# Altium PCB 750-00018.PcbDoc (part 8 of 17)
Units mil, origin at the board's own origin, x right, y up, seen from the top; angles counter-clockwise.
Board outline 7086.64 x 6299.21 mil, 8 copper layers (Top Layer, L2, L3, L4, L5, L6, L7, Bottom Layer), stack 60.6 mil thick; 1356 components, 1054 nets, 4851 pads, 4296 vias.
Unrouted connection lines stored in the file: 12.
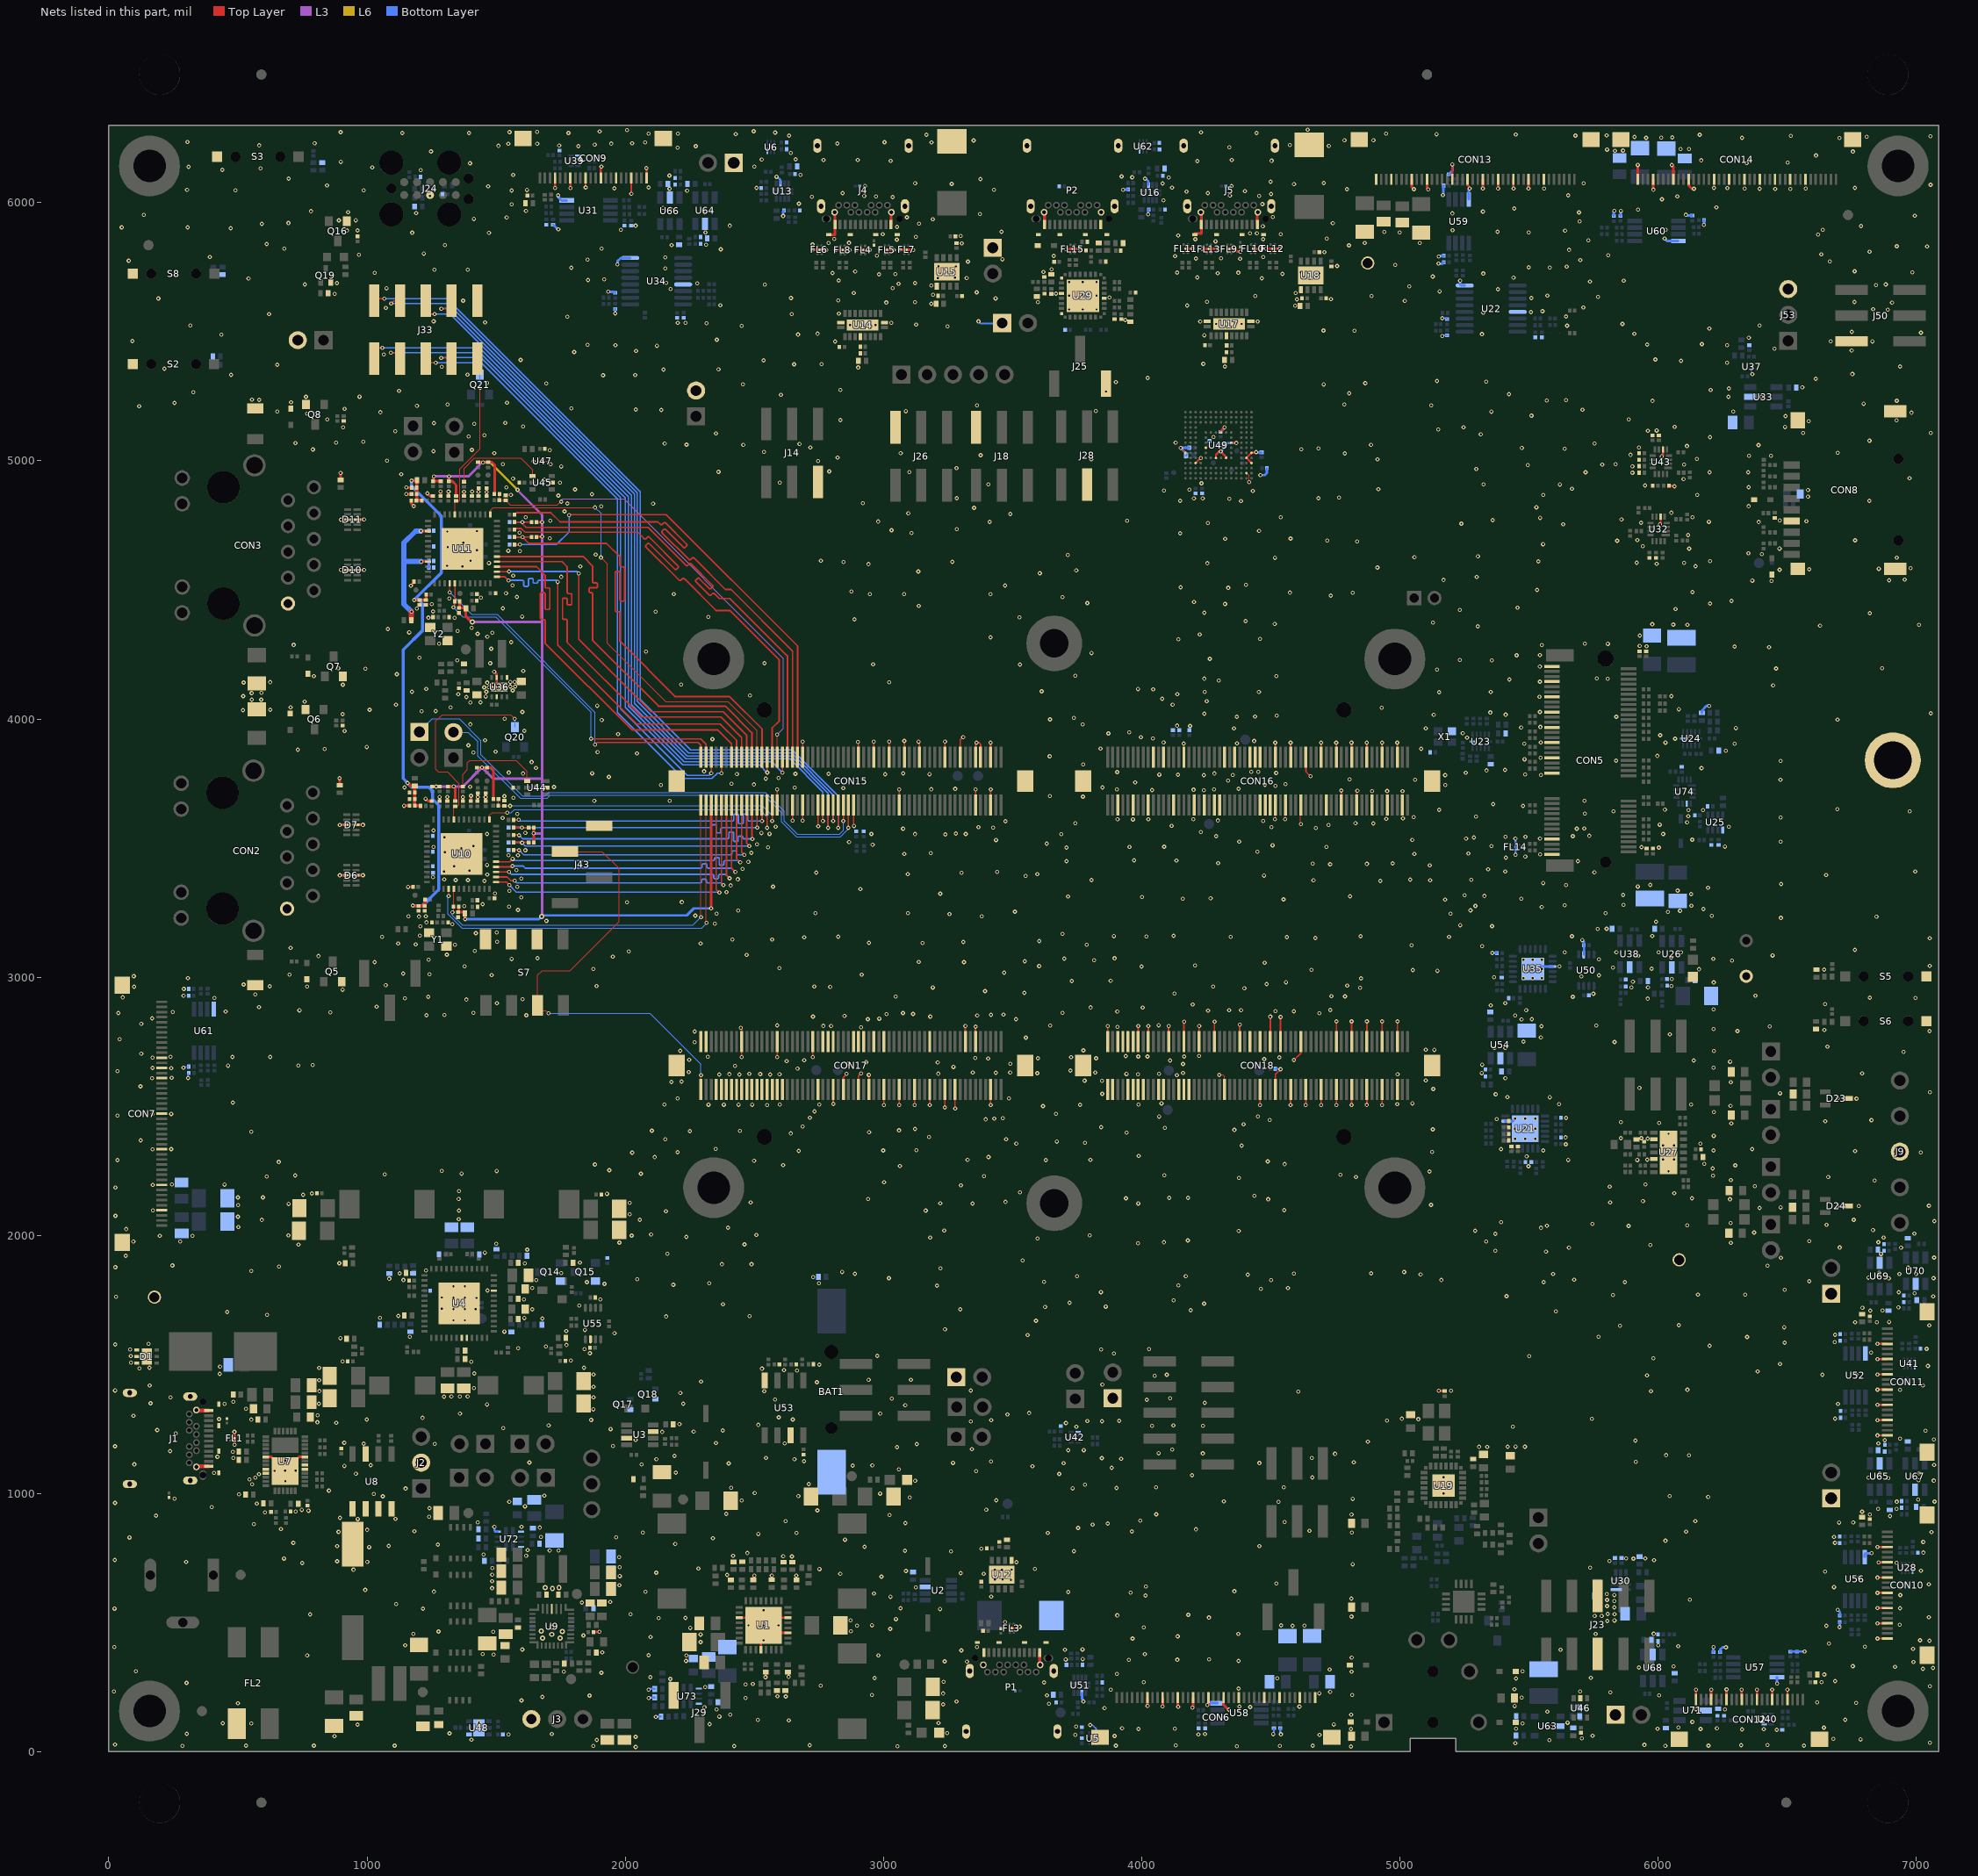
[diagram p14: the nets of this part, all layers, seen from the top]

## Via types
v1: diameter 16, hole 8, Top Layer to Bottom Layer, tented both sides, 3994 vias
v2: diameter 20, hole 10, Top Layer to Bottom Layer, tented both sides, 266 vias
v3: diameter 14, hole 7.87, Top Layer to Bottom Layer, tented both sides, 24 vias
v4: diameter 22, hole 12, Top Layer to Bottom Layer, tented both sides, 8 vias
v5: diameter 24, hole 12, Top Layer to Bottom Layer, tented both sides, 4 vias

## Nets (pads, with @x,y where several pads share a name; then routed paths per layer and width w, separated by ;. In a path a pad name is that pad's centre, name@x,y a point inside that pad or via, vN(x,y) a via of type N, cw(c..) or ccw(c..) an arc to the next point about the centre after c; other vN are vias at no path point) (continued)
ETH1_VDDA_1V8: C126.2 C127.1 C128.1 C129.1 C130.1 C152.2 C153.1 C154.1 C155.1 C156.1 FB2.2 FB4.2 R76.1 R77.1 R109.1 R110.1 | length 2343.3
  Top Layer w10: v1(1182.52,4461.06) 1182.76,4461.3 C155.1@1227.55,4461.3 1228.79,4462.53 R109.1@1228.79,4482.59
  Top Layer w12: v1(1157.01,3752.13) 1168.43,3740.72 FB2.2@1184.36,3740.72 C126.2@1184.36,3714.83 ; v1(1172.22,4923.13) 1173.37,4924.29 FB4.2@1193.87,4924.29 1192.04,4922.46 C152.2@1192.04,4896.05 1192.04,4872.01 1192.03,4847.98 C156.1@1191.83,4847.79 ; v1(1176.99,3277.43) 1198.48,3277.43 C128.1@1199.45,3276.46 ; C126.2@1184.47,3714.83 C127.1@1184.46,3689.91 C129.1@1184.46,3664.62 1206.53,3664.62 R77.1@1207.75,3663.4 ; C156.1@1191.77,4847.72 C156.1@1191.83,4847.79 ; C128.1@1199.46,3276.44 C130.1@1223.51,3276.44 1224.85,3277.78 R76.1@1224.85,3300.28 ; R110.1@1212.96,4847.79 C156.1@1191.83,4847.79
  Bottom Layer w12: v1(1172.22,4923.13) 1172.22,4901.66 1287.77,4786.11 1287.77,4566.31 v1(1182.52,4461.06) 1199,4461.06 1215.45,4444.6 1215.45,4343.33 1139.41,4267.29 1139.41,3769.73 v1(1157.01,3752.13) 1174.1,3735.04 1240.29,3735.04 1253.93,3721.4 1253.93,3690.35 1277.82,3666.46 1277.82,3339.79 1215.46,3277.43 v1(1176.99,3277.43)
ETH1_VDDA_2V5: C157.2 C158.1 C159.1 FB17.2 U11.3 U11.9 | length 603.7
  Top Layer w10: v1(1208.97,4727.97) 1209.06,4727.88 U11.3@1235.62,4727.88 ; v1(1209.42,4609.98) 1209.63,4609.77 U11.9@1235.62,4609.77
  Top Layer w20: FB17.2@1171.69,4382.32 1171.69,4414.81 v1(1172.16,4415.27)
  Bottom Layer w10: v1(1208.97,4727.97) 1210.23,4729.23 C157.2@1238.84,4729.23 ; v1(1209.42,4609.98) 1211.53,4612.08 C158.1@1238.84,4612.08 C159.1@1238.84,4586.7 C159.1@1238.84,4586.7
  Bottom Layer w20: v1(1172.16,4415.27) 1142.74,4444.68 1142.74,4610.83 ; v1(1208.97,4727.97) 1188.14,4727.97 1142.74,4682.58 1142.74,4610.83 ; v1(1209.42,4609.98) 1143.6,4609.98 1142.74,4610.83
ETH_A_(R)(G)MII_COL: CON15.50 J33.5 | length 3000.7
  Top Layer w5: J33.5@1227.36,5620.08 1227.36,5578.09 1236.71,5568.73 v1(1261.51,5568.73) ; v1@2765.75,3604.75 CON15.50@2765.75,3666.88
  Bottom Layer w5: v1(1261.51,5568.73) 1321.48,5568.73 2024.19,4866.02 2024.19,4055.28 2233.92,3845.55 2637.36,3845.55 2765.66,3717.26 2765.66,3619.21 v1(2765.66,3604.65)
ETH_A_(R)(G)MII_CRS: CON15.52 J33.3 | length 3044.6
  Top Layer w5: v1(1287.25,5588.73) 1326.4,5588.73 1327.36,5589.69 J33.3@1327.36,5620.08 ; v1(2785.34,3578.53) 2785.44,3578.62 CON15.52@2785.44,3666.88
  Bottom Layer w5: v1(1287.25,5588.73) 1288.93,5590.41 1315.62,5590.41 2035.21,4870.82 2035.21,4060.61 2239.9,3855.92 2642.01,3855.92 2785.34,3712.59 2785.34,3629.5 v1(2785.34,3578.53)
ETH_A_(R)(G)MII_RX_CLK: C123.1 CON15.18 R83.1 | length 1140.6
  Top Layer w6: R83.1@1567.63,3492.99 1587.57,3492.99 v1(1588.53,3492.03) ; CON15.18@2450.79,3666.88 2450.79,3484.42 v1(2461.15,3474.06)
  Bottom Layer w6: C123.1@1567.62,3492.99 1587.57,3492.99 v1(1588.53,3492.03) 1606.51,3474.06 2404.16,3474.06 2407.16,3474.06 ccw(c2407.16,3480.06) 2413.16,3480.06 2413.16,3484.47 cw(c2417.66,3484.47) 2417.66,3488.97 2426.66,3488.97 cw(c2426.66,3484.47) 2431.16,3484.47 2431.16,3480.06 ccw(c2437.16,3480.06) 2437.16,3474.06 2451.85,3474.06 v1(2461.15,3474.06)
ETH_A_(R)(G)MII_RX_DV(_ER): CON15.30 R80.1 R100.2 R101.1 | length 1185
  Top Layer w4: R100.2@1508.75,3689.35 1508.75,3665.42 R80.1@1508.18,3664.85 1530.83,3664.85 R101.1@1531.89,3663.79 1553.89,3663.79 v1(1554.1,3663.59)
  Top Layer w5: v1@2568.9,3604.75 CON15.30@2568.9,3666.88
  Bottom Layer w4: v1(1554.1,3663.59) 2531.25,3663.59 2568.81,3626.03 v1(2568.81,3604.65)
ETH_A_(R)(G)MII_RX_ER: CON15.54 J33.7 | length 3176.3
  Top Layer w5: v1(1093.27,5608.79) 1104.56,5620.08 J33.7@1127.36,5620.08 ; v1(2805.03,3604.65) CON15.54@2805.12,3666.88
  Bottom Layer w5: v1(1093.27,5608.79) 1313.33,5608.79 2045.84,4876.28 2045.84,4068.52 2245.54,3868.82 2643.86,3868.82 2805.03,3707.65 v1(2805.03,3604.65)
ETH_A_(R)(G)MII_RXD2: CON15.24 R88.1 R96.2 R105.1 | length 1140.6
  Top Layer w6: R88.1@1567.63,3579.89 1599.22,3579.89 v1(1599.66,3579.46) 1625.81,3579.46 R96.2@1626.25,3579.89 ; CON15.24@2509.85,3666.88 2509.85,3580.17 v1(2510.88,3579.13)
  Bottom Layer w6: R105.1@1567.63,3579.89 1599.22,3579.89 v1(1599.66,3579.46) 2324.78,3579.46 2327.78,3579.46 ccw(c2327.78,3585.46) 2333.78,3585.46 2333.78,3586.15 cw(c2338.28,3586.15) 2338.28,3590.65 2347.28,3590.65 cw(c2347.28,3586.15) 2351.78,3586.15 2351.78,3563.55 ccw(c2356.28,3563.55) 2356.28,3559.05 2365.28,3559.05 ccw(c2365.28,3563.55) 2369.78,3563.55 2369.78,3573.46 cw(c2375.78,3573.46) 2375.78,3579.46 2405.29,3579.46 v1@2510.56,3579.46
ETH_A_(R)(G)MII_RXD3: CON15.26 R89.1 | length 1140.6
  Top Layer w6: R89.1@1567.63,3608.86 1585.88,3608.86 v1(1587.21,3610.2) ; v1(2529.44,3604.65) 2529.53,3604.75 CON15.26@2529.53,3666.88
  Bottom Layer w6: v1(1587.21,3610.2) 1592.76,3604.65 2411.2,3604.65 2414.2,3604.65 ccw(c2414.2,3610.65) 2420.2,3610.65 2420.2,3627.86 cw(c2424.7,3627.86) 2424.7,3632.36 2433.7,3632.36 cw(c2433.7,3627.86) 2438.2,3627.86 2438.2,3599.15 ccw(c2442.7,3599.15) 2442.7,3594.65 2451.7,3594.65 ccw(c2451.7,3599.15) 2456.2,3599.15 2456.2,3627.65 cw(c2460.7,3627.65) 2460.7,3632.15 2469.7,3632.15 cw(c2469.7,3627.65) 2474.2,3627.65 2474.2,3610.65 ccw(c2480.2,3610.65) 2480.2,3604.65 2501.15,3604.65 v1(2529.44,3604.65)
ETH_A_(R)(G)MII_TX_CLK: CON15.16 U10.29 | length 1227.6
  Top Layer w6: U10.29@1499.4,3447.14 1552.83,3447.14 v1(1563.74,3458.06) ; CON15.16@2431.1,3666.88 2431.1,3459.17 v1(2444.95,3445.32)
  Bottom Layer w6: v1(1563.74,3458.06) 1570.17,3451.63 2336.8,3451.63 2339.8,3451.63 ccw(c2339.8,3457.63) 2345.8,3457.63 2345.8,3458.55 cw(c2350.3,3458.55) 2350.3,3463.05 2359.3,3463.05 cw(c2359.3,3458.55) 2363.8,3458.55 2363.8,3438.64 ccw(c2368.3,3438.64) 2368.3,3434.14 2377.3,3434.14 ccw(c2377.3,3438.64) 2381.8,3438.64 2381.8,3445.63 cw(c2387.8,3445.63) 2387.8,3451.63 2418.67,3451.63 2438.65,3451.63 v1(2444.95,3445.32)
ETH_A_(R)(G)MII_TX_EN(_ER): CON15.28 U10.37 | length 1242.4
  Top Layer w4: U10.37@1473.81,3610.53 1473.81,3626.11 1484.51,3636.82 v1(1542.93,3636.82)
  Top Layer w5: v1(2549.12,3578.53) 2549.22,3578.62 CON15.28@2549.22,3666.88
  Bottom Layer w4: v1(1542.93,3636.82) 1557.9,3636.82 1570.42,3649.34 2519.52,3649.34 2549.12,3619.73 v1(2549.12,3578.53)
ETH_A_(S)(R)(G)MII_RXD0: CON15.20 R84.1 R97.1 R104.1 | length 1141
  Top Layer w6: R84.1@1567.63,3521.96 1598.93,3521.96 v1(1600.05,3520.83) 1601.18,3521.96 R97.1@1626.25,3521.96 ; CON15.20@2470.48,3666.88 2470.48,3518.1 v1(2480.46,3508.12)
  Bottom Layer w6: R104.1@1567.63,3521.96 1598.93,3521.96 v1(1600.05,3520.83) 1612.77,3508.12 2394.91,3508.12 2458.85,3508.12 v1(2480.46,3508.12)
ETH_A_(S)(R)(G)MII_RXD1: CON15.22 R86.1 | length 1140.6
  Top Layer w6: R86.1@1567.63,3550.93 1587.9,3550.93 v1(1589.02,3549.8) ; CON15.22@2490.16,3666.88 2490.16,3537.87 v1(2492.44,3535.59)
  Bottom Layer w6: v1(1589.02,3549.8) 1603.23,3535.59 2392.13,3535.59 2395.13,3535.59 ccw(c2395.13,3541.59) 2401.13,3541.59 2401.13,3557.63 cw(c2405.63,3557.63) 2405.63,3562.13 2414.63,3562.13 cw(c2414.63,3557.63) 2419.13,3557.63 2419.13,3530.17 ccw(c2423.63,3530.17) 2423.63,3525.67 2432.63,3525.67 ccw(c2432.63,3530.17) 2437.13,3530.17 2437.13,3541.59 cw(c2441.63,3541.59) 2441.63,3546.09 2450.63,3546.09 cw(c2450.63,3541.59) 2455.13,3541.59 ccw(c2461.13,3541.59) 2461.13,3535.59 2481.35,3535.59 v1(2492.44,3535.59)
ETH_A_(S)(R)(G)MII_TXD0: CON15.14 U10.28 | length 1227.6
  Top Layer w6: U10.28@1499.4,3427.46 1560.26,3427.46 v1(1563.59,3430.79) ; CON15.14@2411.42,3666.88 2411.42,3422.48 v1(2426.28,3407.62)
  Bottom Layer w6: v1(1563.59,3430.79) 1604.27,3430.79 1612.83,3422.23 2288.62,3422.23 2291.62,3422.23 ccw(c2291.62,3428.23) 2297.62,3428.23 2297.62,3434.4 cw(c2302.12,3434.4) 2302.12,3438.9 2311.12,3438.9 cw(c2311.12,3434.4) 2315.62,3434.4 2315.62,3428.23 ccw(c2321.62,3428.23) 2321.62,3422.23 2349.74,3422.23 2411.68,3422.23 v1(2426.28,3407.62)
ETH_A_(S)(R)(G)MII_TXD1: CON15.12 U10.27 | length 1227.6
  Top Layer w6: U10.27@1499.4,3407.77 1549.94,3407.77 v1(1550.1,3407.61) ; CON15.12@2391.73,3666.88 2391.73,3395.05 v1(2403.74,3383.05)
  Bottom Layer w6: v1(1550.1,3407.61) 1559.72,3397.99 2315.96,3397.99 2336.96,3397.99 cw(c2336.96,3391.99) 2342.96,3391.99 2342.96,3385.88 ccw(c2347.46,3385.88) 2347.46,3381.38 2356.46,3381.38 ccw(c2356.46,3385.88) 2360.96,3385.88 2360.96,3391.99 cw(c2366.96,3391.99) 2366.96,3397.99 2380.74,3397.99 2388.8,3397.99 v1(2403.74,3383.05)
ETH_A_(S)(R)(G)MII_TXD2: CON15.10 U10.26 | length 1227.6
  Top Layer w6: U10.26@1499.4,3388.09 1542.7,3388.09 1557.13,3373.66 v1(1572.04,3373.66) ; CON15.10@2372.05,3666.88 2372.05,3364.2 v1(2379.93,3356.32)
  Bottom Layer w6: v1(1572.04,3373.66) 1580.86,3364.85 2286.83,3364.85 2289.83,3364.85 ccw(c2289.83,3370.85) 2295.83,3370.85 2295.83,3374.9 cw(c2300.33,3374.9) 2300.33,3379.4 2309.33,3379.4 cw(c2309.33,3374.9) 2313.83,3374.9 2313.83,3370.85 ccw(c2319.83,3370.85) 2319.83,3364.85 2335.5,3364.85 2371.41,3364.85 v1(2379.93,3356.32)
ETH_A_(S)(R)(G)MII_TXD3: CON15.8 U10.25 | length 1227.4
  Top Layer w6: U10.25@1499.4,3368.4 1538.78,3368.4 v1(1551.03,3356.16) ; CON15.8@2352.36,3666.88 2352.36,3340 v1(2365.02,3327.34)
  Bottom Layer w6: v1(1551.03,3356.16) 1577.77,3329.41 2362.95,3329.41 v1(2365.02,3327.34)
ETH_A_INTR: Q20.3 R79.1 U10.44 | length 808
  Top Layer w4: U10.44@1336.01,3610.53 1336.01,3658.76 R79.1@1339.4,3662.14 ; R79.1@1340.75,3662.08 R79.1@1341.29,3662.08 1350.69,3662.08 1356.27,3667.67 1356.27,3749.96 1310.79,3795.44 1276.57,3795.44 1266.16,3805.85 1266.16,3992.21 1290.6,4016.65 1555.85,4016.65 v1(1571.43,4001.08)
  Bottom Layer w4: v1(1571.43,4001.08) 1573,3999.51 Q20.3@1573,3968.39
"ETH_A_INTR / GPIO_A_2": CON15.58 J32.1 | length 2018.9
  Top Layer w5: v1@2844.49,3604.75 CON15.58@2844.49,3666.88
  Bottom Layer w4: J32.1@1202.44,3949.86 1202.44,3951.67 1251.52,4000.75 1357.04,4000.75 1441.03,3916.76 1441.03,3861.89 1601.72,3701.2 1688.82,3701.2 1702.93,3715.31 2542.34,3715.31 2615.37,3642.28 2615.37,3605.52 2667.13,3553.76 2829.47,3553.76 2844.4,3568.69 v1(2844.4,3604.65)
ETH_A_RST: R87.2 U44.4 | length 389.1
  Top Layer w4: R87.2@1371.42,3738.58 1371.42,3785.65 1388.69,3802.92 1388.69,3831.15 1397.71,3840.16 1576.18,3840.16 1619.67,3796.67 U44.4@1619.67,3760.03
"ETH_A_RST / GPIO_A_1": CON15.60 J31.2 | length 1867.7
  Top Layer w5: v1@2864.18,3578.53 CON15.60@2864.18,3666.88
  Bottom Layer w4: J31.2@1334.56,3949.05 1392.19,3949.05 1428.89,3912.35 1428.89,3856.97 1593.38,3692.47 1697.35,3692.47 1709.7,3704.82 2538,3704.82 2604.88,3637.94 2604.88,3601.18 2662.79,3543.27 2833.81,3543.27 2864.08,3573.54 v1(2864.08,3578.53)
ETH_A_SDP: CON15.56 J33.9 | length 3281.2
  Top Layer w5: J33.9@1027.36,5620.08 1035.09,5627.81 v1(1066.65,5627.81) ; v1(2824.71,3578.53) 2824.81,3578.62 CON15.56@2824.81,3666.88
  Bottom Layer w5: v1(1066.65,5627.81) 1309.51,5627.81 2057.45,4879.88 2057.45,4076.09 2253.45,3880.08 2646.82,3880.08 2824.81,3702.1 2824.81,3625.54 2824.81,3578.62 v1(2824.71,3578.53)
ETH_B_(R)(G)MII_COL: CON15.9 J33.6 | length 2374.4
  Top Layer w5: J33.6@1227.36,5395.68 1243.69,5379.34 v1(1266.3,5379.34) ; v1@2372.05,3789.78 CON15.9@2372.05,3851.92
  Bottom Layer w5: v1(1266.3,5379.34) 1443.09,5379.34 1969.16,4853.27 1969.16,4025.08 2225.17,3769.07 2335.83,3769.07 2356.44,3789.69 v1(2372.14,3789.69)
ETH_B_(R)(G)MII_CRS: CON15.5 J33.4 | length 2301.5
  Top Layer w5: v1(1286.96,5398.18) 1324.85,5398.18 J33.4@1327.36,5395.68 ; v1@2332.68,3789.78 CON15.5@2332.68,3851.92
  Bottom Layer w5: v1(1286.96,5398.18) 1288.07,5399.29 1440.35,5399.29 1981.33,4858.31 1981.33,4040.9 2239.91,3782.32 2325.4,3782.32 v1(2332.77,3789.69)
ETH_B_(R)(G)MII_RX_CLK: C149.1 CON15.39 R116.1 | length 1844.5
  Top Layer w6: R116.1@1571.57,4675.31 1591.86,4675.31 v1(1592.2,4675.64) ; v1(1782.32,4789.94) 1783.71,4791.33 2158.88,4791.33 2667.33,4282.88 CON15.39@2667.33,3851.92
  Bottom Layer w6: C149.1@1571.57,4675.31 1591.86,4675.31 v1(1592.2,4675.64) 1733.46,4675.64 1782.32,4724.49 v1(1782.32,4789.94)
ETH_B_(R)(G)MII_RX_DV(_ER): CON15.31 R113.1 R133.2 R134.1 | length 1789.6
  Top Layer w4: R133.2@1512.7,4871.67 1512.69,4847.74 R113.1@1512.12,4847.17 R134.1@1533.32,4847.17 ; R134.1@1536.93,4846.48 1555.11,4828.3 1737.3,4828.3 1750.81,4841.81 v1(1752,4841.81) ; CON15.31@2588.59,3851.92 v1@2588.59,3939.34
  L3 w4: v1(1752,4841.81) 1752,4846.6 1757.25,4851.85 1994.45,4851.85 2612.86,4233.43 2612.86,3963.62 v1(2588.68,3939.43)
ETH_B_(R)(G)MII_RX_ER: CON15.27 J33.8 | length 2718.8
  Top Layer w5: v1(1092.36,5418.99) 1118.25,5418.99 1127.36,5409.88 J33.8@1127.36,5395.68 ; CON15.27@2549.22,3851.92 2549.22,3793.4 v1(2549.92,3792.7)
  Bottom Layer w5: v1(1092.36,5418.99) 1437.24,5418.99 2000.21,4856.03 2000.21,4045 2223.08,3822.12 2520.5,3822.12 v1(2549.92,3792.7)
ETH_B_(R)(G)MII_RXD2: CON15.35 R121.1 R129.2 R138.1 | length 1915.5
  Top Layer w6: R121.1@1571.57,4762.21 1601.14,4762.21 v1(1601.35,4762.42) ; R129.2@1636.48,4762.21 1636.26,4762.42 v1(1601.35,4762.42) ; 2234.93,4595.41 2232.81,4597.53 2088.01,4742.34 1615.42,4742.34 1601.35,4756.41 v1(1601.35,4762.42) ; 2234.95,4595.39 ccw(c2238.75,4599.23) 2242.56,4595.4 2247.68,4600.52 cw(c2251.48,4596.69) 2255.3,4600.5 2337.45,4518.35 cw(c2333.63,4514.53) 2337.45,4510.71 2332.36,4505.62 cw(c2328.54,4509.44) 2324.72,4505.62 2286.47,4543.88 ccw(c2282.65,4540.06) 2278.83,4543.88 2273.74,4538.79 ccw(c2277.56,4534.97) 2273.74,4531.15 2324.75,4480.14 ccw(c2328.54,4483.98) 2332.35,4480.15 2337.47,4485.27 cw(c2341.27,4481.44) 2345.09,4485.26 2347.21,4483.14 2363.31,4467.03 2405.41,4467.03 2627.96,4244.48 CON15.35@2627.96,3851.92
  Bottom Layer w6: R138.1@1571.57,4762.21 1601.14,4762.21 v1(1601.35,4762.42)
ETH_B_(R)(G)MII_RXD3: CON15.37 R122.1 | length 1980.3
  Top Layer w6: R122.1@1571.57,4791.18 1579.2,4798.81 1712.11,4798.81 1747.54,4763.38 2126.25,4763.38 2133.81,4755.82 2135.93,4753.7 2135.97,4753.66 ccw(c2139.75,4757.52) 2143.55,4753.68 2148.67,4758.8 cw(c2152.47,4754.97) 2156.28,4758.8 2237.25,4677.83 cw(c2233.43,4674.01) 2237.25,4670.19 2232.16,4665.1 cw(c2228.34,4668.92) 2224.52,4665.1 2156.29,4733.33 ccw(c2152.47,4729.52) 2148.66,4733.33 2143.56,4728.24 ccw(c2147.38,4724.42) 2143.56,4720.61 2246.2,4617.97 ccw(c2250,4621.81) 2253.8,4617.97 2258.92,4623.09 cw(c2262.73,4619.26) 2266.55,4623.08 2268.67,4620.96 2388.19,4501.44 2409.23,4501.44 2647.64,4263.03 CON15.37@2647.64,3851.92
ETH_B_(R)(G)MII_TX_CLK: CON15.21 U11.29 | length 1583
  Top Layer w6.5: U11.29@1503.34,4629.46 1836.36,4629.46 1873.24,4592.58 1873.24,4536.89 1873.24,4533.64 ccw(c1879.74,4533.64) 1879.74,4527.14 1887.46,4527.14 cw(c1887.46,4522.51) 1892.08,4522.51 1892.08,4513.26 cw(c1887.46,4513.26) 1887.46,4508.64 1864.92,4508.64 ccw(c1864.92,4504.01) 1860.3,4504.01 1860.3,4494.76 ccw(c1864.92,4494.76) 1864.92,4490.14 1866.74,4490.14 cw(c1866.74,4483.64) 1873.24,4483.64 1873.24,4370.34 1873.24,4305.17 2128.82,4049.59 2387.57,4049.59 2490.16,3947 CON15.21@2490.16,3851.92
ETH_B_(R)(G)MII_TX_EN(_ER): CON15.23 U11.37 | length 1794.1
  Top Layer w4: U11.37@1477.75,4792.84 1477.75,4808.73 1488.26,4819.23 v1(1883.31,4819.23) ; v1(1906.03,4625.37) 1931.01,4600.39 1931.01,4292.63 2156.12,4067.51 2397.69,4067.51 2509.85,3955.35 CON15.23@2509.85,3851.92
  Bottom Layer w4: v1(1883.31,4819.23) 1906.03,4796.52 v1(1906.03,4625.37)
ETH_B_(S)(R)(G)MII_RXD0: CON15.25 R117.1 R130.2 R137.1 | length 1914.8
  Top Layer w6: R117.1@1571.57,4704.27 1601.85,4704.27 v1(1602.09,4704.51) ; R130.2@1636.48,4705.15 1602.73,4705.15 v1(1602.09,4704.51) ; CON15.25@2529.53,3851.92 2529.53,3961.7 2404.71,4086.53 2193.84,4086.53 1979.16,4301.21 1979.16,4407.37 1979.16,4410.37 ccw(c1973.76,4410.37) 1973.76,4415.77 1966.56,4415.77 cw(c1966.56,4421.17) 1961.16,4421.17 1961.16,4566.12 cw(c1966.56,4566.12) 1966.56,4571.52 1973.76,4571.52 cw(c1973.76,4566.12) 1979.16,4566.12 1979.16,4462.3 ccw(c1984.56,4462.3) 1984.56,4456.9 1991.76,4456.9 ccw(c1991.76,4462.3) 1997.16,4462.3 1997.16,4584.12 ccw(c1991.76,4584.12) 1991.76,4589.52 1984.56,4589.52 cw(c1984.56,4594.92) 1979.16,4594.92 1979.16,4597.92 1979.16,4627.75 1926.78,4680.13 1626.47,4680.13 v1(1602.09,4704.51)
  Bottom Layer w6: R137.1@1571.57,4704.27 1601.85,4704.27 v1(1602.09,4704.51)
ETH_B_(S)(R)(G)MII_RXD1: CON15.29 R119.1 | length 1977.6
  Top Layer w6: R119.1@1571.57,4733.24 1575.93,4737.61 1597.41,4737.61 1611.74,4723.27 2048.42,4723.27 2070.77,4700.92 2072.89,4698.8 2072.93,4698.76 ccw(c2076.71,4702.62) 2080.51,4698.79 2085.63,4703.91 cw(c2089.44,4700.07) 2093.24,4703.91 2203.98,4593.17 cw(c2200.16,4589.35) 2203.98,4585.53 2198.88,4580.44 cw(c2195.07,4584.26) 2191.25,4580.44 2093.25,4678.44 ccw(c2089.44,4674.62) 2085.62,4678.44 2080.53,4673.34 ccw(c2084.34,4669.53) 2080.53,4665.71 2208.3,4537.93 ccw(c2212.11,4541.76) 2215.91,4537.93 2221.03,4543.05 cw(c2224.84,4539.22) 2228.65,4543.04 2230.77,4540.91 2351.3,4420.39 2404.61,4420.39 2596.2,4228.81 2596.2,3993.04 2568.9,3965.74 CON15.29@2568.9,3851.92
ETH_B_(S)(R)(G)MII_TXD0: CON15.17 U11.28 | length 1583
  Top Layer w6: U11.28@1503.34,4609.77 1754.83,4609.77 1774.86,4589.74 1774.86,4494.21 1774.86,4491.21 ccw(c1780.26,4491.21) 1780.26,4485.81 1787.46,4485.81 cw(c1787.46,4480.41) 1792.86,4480.41 1792.86,4447.17 cw(c1787.46,4447.17) 1787.46,4441.77 1780.26,4441.77 cw(c1780.26,4447.17) 1774.86,4447.17 1774.86,4462.41 ccw(c1769.46,4462.41) 1769.46,4467.81 1762.26,4467.81 ccw(c1762.26,4462.41) 1756.86,4462.41 1756.86,4391.42 ccw(c1762.26,4391.42) 1762.26,4386.02 1769.46,4386.02 cw(c1769.46,4380.62) 1774.86,4380.62 1774.86,4377.62 1774.86,4296.84 2064.3,4007.41 2371.31,4007.41 2450.79,3927.92 CON15.17@2450.79,3851.92
ETH_B_(S)(R)(G)MII_TXD1: CON15.13 U11.27 | length 1583
  Top Layer w6: U11.27@1503.34,4590.09 1656.61,4590.09 1689.51,4557.19 1689.51,4516.07 1689.51,4513.07 ccw(c1694.91,4513.07) 1694.91,4507.67 1702.11,4507.67 cw(c1702.11,4502.27) 1707.51,4502.27 1707.51,4429.7 cw(c1702.11,4429.7) 1702.11,4424.3 1694.91,4424.3 cw(c1694.91,4429.7) 1689.51,4429.7 1689.51,4484.27 ccw(c1684.11,4484.27) 1684.11,4489.67 1676.91,4489.67 ccw(c1676.91,4484.27) 1671.51,4484.27 1671.51,4390.9 ccw(c1676.91,4390.9) 1676.91,4385.5 1684.11,4385.5 cw(c1684.11,4380.1) 1689.51,4380.1 1689.51,4377.1 1689.51,4293.67 2025.33,3957.84 2357.73,3957.84 2411.42,3904.15 CON15.13@2411.42,3851.92
ETH_B_(S)(R)(G)MII_TXD2: CON15.19 U11.26 | length 1464.8
  Top Layer w6: U11.26@1503.34,4570.4 1548.87,4570.4 v1(1550.01,4571.54) ; v1(1820.15,4563.95) 1820.15,4308.49 2100.67,4027.97 2378.87,4027.97 2470.48,3936.37 CON15.19@2470.48,3851.92
  Bottom Layer w6: v1(1550.01,4571.54) 1812.56,4571.54 v1(1820.15,4563.95)
ETH_B_(S)(R)(G)MII_TXD3: CON15.15 U11.25 | length 1464.1
  Top Layer w6: U11.25@1503.34,4550.72 1533.94,4550.72 v1(1547.72,4536.94) ; v1@1738.43,4530.4 1738.43,4286.91 2044.82,3980.52 2367.88,3980.52 2431.11,3917.29 CON15.15@2431.1,3851.92
  Bottom Layer w6: v1(1547.72,4536.94) 1579.96,4536.94 1600.96,4536.94 cw(c1600.96,4530.94) 1606.96,4530.94 1606.96,4517.86 ccw(c1611.46,4517.86) 1611.46,4513.36 1620.46,4513.36 ccw(c1620.46,4517.86) 1624.96,4517.86 1624.96,4539.59 cw(c1629.46,4539.59) 1629.46,4544.09 1638.46,4544.09 cw(c1638.46,4539.59) 1642.96,4539.59 1642.96,4530.94 ccw(c1647.46,4530.94) 1647.46,4526.44 1656.46,4526.44 ccw(c1656.46,4530.94) 1660.96,4530.94 cw(c1666.96,4530.94) 1666.96,4536.94 1707.22,4536.94 1732.62,4536.94 v1(1738.79,4530.77)
ETH_B_INTR: Q21.3 R112.1 U11.44 | length 588.2
  Top Layer w4: U11.44@1339.95,4792.84 1339.95,4841.07 R112.1@1343.34,4844.46 ; R112.1@1344.69,4844.4 1356.67,4844.4 1360.06,4847.79 1360.06,4968.86 1438.06,5046.85 v1(1438.06,5283.07)
  Bottom Layer w4: Q21.3@1437.03,5333.42 1437.03,5284.1 v1(1438.06,5283.07)
ETH_B_MDC: CON15.1 U11.16 | length 1379.8
  Top Layer w4: v1@1320.01,4490.15 v1(1320.27,4490.41) U11.16@1320.27,4525.13
  Top Layer w5: v1(1883.07,3900.33) 1891.85,3909.11 2282.44,3909.11 2293.31,3898.24 CON15.1@2293.31,3851.92
  Bottom Layer w4: v1(1320.27,4490.41) 1405.89,4404.79 1503.14,4404.79 1882.96,4024.98 v1@1882.96,3900.44
ETH_B_MDIO: CON15.3 R111.1 U11.17 | length 1404.7
  Top Layer w5: v1(1334.34,4432.75) 1339.23,4437.64 R111.1@1339.23,4455.46 1339.95,4456.18 U11.17@1339.95,4525.13 ; v1(1867.89,3923.41) 2292.62,3923.41 2312.99,3903.03 CON15.3@2312.99,3851.92
  Bottom Layer w4: v1(1334.34,4432.75) 1371.39,4395.69 1499.37,4395.69 1867.89,4027.18 v1(1867.89,3923.41)
ETH_B_RST: R120.2 U45.4 | length 375.9
  Top Layer w4: R120.2@1375.56,4918.9 1375.56,4969.99 1415.53,5009.96 1595.71,5009.96 1641.13,4964.54 U45.4@1641.13,4940.7
ETH_B_SDP: CON15.33 J33.10 | length 2846.6
  Top Layer w5: J33.10@1027.36,5395.68 1022.18,5400.85 1022.18,5438 1058.84,5438 v1(1059.24,5437.6) ; CON15.33@2608.27,3850.35 2608.27,3793.19 v1(2609.14,3792.32)
  Bottom Layer w5: v1(1059.24,5437.6) 1435.93,5437.6 1437.5,5436.02 2012.44,4861.09 2012.44,4050.06 2228.15,3834.35 2567.11,3834.35 v1(2609.14,3792.32)
ETH_IOPWR: C118.2 C144.2 CON15.6 FB1.1 FB3.1 R78.2 R79.2 R93.1 R94.1 R95.1 R96.1 R97.2 R98.1 R99.1 R100.1 R111.2 R112.2 R126.1 R127.1 R128.1 R129.1 R130.1 R131.1 R132.1 R133.1 | length 5127.8
  Top Layer w10: R93.1@1252.75,3738.33 v1(1267.14,3738.33) R94.1@1281.53,3738.33 ; v1(1258.86,4939.56) 1255.64,4936.35 R126.1@1255.64,4920.77 R127.1@1285.47,4920.77 ; R95.1@1313.17,3738.58 1335.17,3738.58 v1(1335.6,3739.02) 1340.75,3733.87 R79.2@1340.75,3681.77 ; v1(1317.4,4939.67) 1316.62,4938.89 R128.1@1316.62,4920.77 1330,4920.77 1344.76,4906.02 R112.2@1344.76,4864.31 ; R78.2@1354.97,3273.14 1354.97,3254.69 C118.2@1352.63,3252.34 1373.05,3252.34 FB1.1@1378.81,3246.58 1378.81,3225.92 v1(1379.76,3224.97) ; R111.2@1358.92,4455.46 1358.92,4432.92 C144.2@1356.39,4430.39 1381.26,4430.39 FB3.1@1382.75,4428.89 1382.75,4396.77 1403.21,4376.31 v2(1407.5,4376.31) ; R98.1@1425.9,3811.91 v1(1445.31,3811.91) R99.1@1464.72,3811.91 1481.18,3811.91 1489.07,3804.02 R100.1@1489.07,3689.35 ; R131.1@1429.85,4994.23 v1(1449.25,4994.23) R132.1@1468.66,4994.23 1484.49,4994.23 1494.75,4983.97 1494.75,4873.4 R133.1@1493.01,4871.67 ; R97.2@1645.93,3521.96 1645.93,3556.46 v1(1645.28,3557.11) 1645.93,3557.77 R96.1@1645.93,3579.89 ; R130.1@1656.16,4705.15 1676.62,4705.15 v1(1677.86,4706.4) ; R129.1@1656.16,4762.21 v1(1677.98,4762.21) ; v1(2332.53,3266.57) 2332.68,3266.72 CON15.6@2332.68,3666.88
  L3 w10: v1(1258.86,4939.56) 1317.29,4939.56 v1(1317.4,4939.67) 1392.67,4939.67 1447.23,4994.23 v1(1449.25,4994.23) ; v1(1267.14,3738.33) 1334.92,3738.33 v1(1335.6,3739.02) 1371.57,3739.02 1444.46,3811.91 v1(1445.31,3811.91) 1488.46,3768.77 1675.19,3768.77 1677.98,3771.56 ; v2(1407.5,4376.31) 1676.62,4376.31 ; v1(1582.73,4887.35) 1582.73,4886.22 1677.98,4790.96 v1(1677.98,4762.21) 1677.98,4706.51 v1(1677.86,4706.4) 1677.98,4706.28 1677.98,3771.56 ; v1(1645.28,3557.11) 1677.98,3557.11 ; v2(1676.23,3235.69) 1677.98,3237.44 1677.98,3557.11 ; 1677.98,3557.11 1677.98,3771.56
  L6 w10: v1(1449.25,4994.23) 1475.85,4994.23 v1(1582.73,4887.35)
  Bottom Layer w10: v1(1379.76,3224.97) 1665.51,3224.97 v2(1676.23,3235.69) 1679.8,3239.26 2238.41,3239.26 2265.72,3266.57 v1(2332.53,3266.57)
ETH_MDC/ETH_A_MDC: CON15.4 U10.16 | length 1589.4
  Top Layer w4: v1(1315.95,3314.48) 1316.33,3314.85 U10.16@1316.33,3342.81 ; CON15.4@2312.99,3666.88 2312.99,3211.93 v1(2314.59,3210.33)
  Bottom Layer w4: v1(1315.95,3314.48) 1313.03,3311.55 1313.03,3244.97 1367.15,3190.85 2296.62,3190.85 2314.59,3208.82 v1(2314.59,3210.33)
ETH_MDIO/ETH_A_MDIO: CON15.2 R78.1 U10.17 | length 1531.6
  Top Layer w4: v1(1330.86,3251.31) 1335.29,3255.75 R78.1@1335.29,3273.14 1336.01,3273.87 U10.17@1336.01,3342.81 ; CON15.2@2293.31,3666.88 2293.31,3232.6 v1(2293.64,3232.27)
  Bottom Layer w4: v1(1330.86,3251.31) 1330.86,3239.52 1369.28,3201.1 2261.81,3201.1 v1@2293.31,3232.6
FORCE_RECOVERY#: CON17.119 J43.3 S7.3 | length 1779.2
  Top Layer w4: S7.3@1660.12,2890.71 1660.12,3008.01 1678.09,3025.99 1786.67,3025.99 1975.98,3215.3 1975.98,3421.37 1910.76,3486.59 J43.3@1765.77,3486.59 ; S7.3@1660.19,2870.96 1692.15,2870.96 v1(1702.74,2860.38) ; CON17.119@2293.31,2565.4 2293.31,2620.12 v1(2293.38,2620.19)
  Bottom Layer w4: v1(1702.74,2860.38) 2095.81,2860.38 2293.38,2662.8 v1(2293.38,2620.19)
GND: BAT1.2 C1.1 C2.1 C3.2 C6.2 C7.2 C8.1 C11.2 C12.2 C13.1 C14.1 C15.1 C16.1 C17.1 C18.1 C19.1 C21.1 C23.2 C24.2 C25.1 C26.2 C27.2 C30.1 C31.2 C33.2 C34.1 C35.2 C36.2 C37.2 C38.2 C39.1 C40.2 C43.1 C44.2 C45.2 C46.1 C48.2 C50.2 C51.1 C52.2 C53.2 C54.1 C55.2 C56.1 C57.2 C59.2 C60.2 C61.1 C62.2 C63.1 C64.1 C65.2 C67.1 C68.2 C69.2 C71.2 C72.2 C73.2 C74.1 C75.1 C76.1 C78.1 C79.1 C80.1 C81.1 C82.1 C83.1 C84.1 C85.1 C86.1 C87.2 C89.2 C90.1 C91.1 C93.1 C94.2 C95.2 C98.2 C99.1 C100.1 C101.2 C102.1 C103.1 C104.1 C105.1 C106.1 C107.1 C108.2 C109.2 C110.2 C111.2 C112.2 C113.2 C114.2 C115.2 C116.2 C117.2 C118.1 C119.1 C120.2 C121.2 C122.2 C123.2 C124.2 C125.2 C126.1 C127.2 C128.2 C129.2 C130.2 C131.1 C132.2 C133.2 C134.1 C135.2 C136.2 C137.2 C138.1 C139.2 C140.2 C141.1 C142.2 C143.1 C144.1 C145.1 C146.2 C147.2 C148.2 C149.2 C150.2 C151.2 C152.1 C153.2 C154.2 C155.2 C156.2 C157.1 C158.2 C159.2 C160.1 C161.2 C162.2 C163.2 C164.1 C165.2 C166.2 C167.1 C168.2 C169.1 C170.2 C171.2 C172.1 C173.2 C174.1 C175.2 C176.1 C177.2 C178.1 C179.2 C180.2 C181.1 C182.1 C183.1 C184.2 C185.1 C186.2 C187.1 C188.2 C189.2 C190.1 C191.1 C199.1 C200.2 C205.1 C206.1 C207.1 C210.1 C215.2 C216.2 C217.2 C218.2 C219.2 C220.2 C221.1 C222.2 C223.2 C224.2 C225.1 C226.1 C227.1 C228.2 C229.2 C230.2 C231.2 C232.2 C233.2 C234.2 C235.1 C236.1 C237.1 C238.1 C239.1 C240.1 C241.1 C242.1 C243.2 C244.2 C245.2 C246.2 C247.2 C250.1 C251.1 C252.1 C253.1 C254.2 C255.2 C256.1 C257.1 C258.1 C259.1 C260.1 C261.1 C262.2 C263.2 C264.2 C265.2 C266.2 C267.2 C268.2 C269.2 C270.1 C271.1 C272.2 C273.2 C274.2 C275.2 C277.2 C278.2 C279.2 C280.1 C281.2 C282.2 C283.2 C284.2 C285.1 C286.2 C287.2 C288.1 C289.2 C290.1 C291.1 C292.1 C293.2 C294.1 C295.1 C296.2 C297.2 C298.2 C299.2 C300.2 C301.2 C302.2 C304.2 C305.2 C307.2 C308.2 C309.2 C310.1 C311.2 C320.1 C321.2 C322.1 C323.1 C324.1 C325.1 C326.2 C327.2 C328.2 C329.2 C330.2 C331.2 C332.2 C333.2 C334.2 C335.2 C336.1 C337.1 C338.1 C339.1 C340.2 C341.2 C342.2 C343.2 C344.2 C345.2 C346.2 C347.2 C348.2 C349.2 C350.2 C351.2 C352.2 C353.2 C354.2 C355.2 C356.2 C357.2 C358.2 C359.2 C360.2 C361.2 C362.2 C363.2 C364.2 C365.2 C366.2 C367.2 C368.2 C369.1 C370.2 C371.2 C372.2 C373.2 C374.2 C375.2 C376.2 C377.2 C378.2 C379.2 C380.2 C381.2 C382.2 C383.2 C384.2 C385.2 C386.2 C387.2 C388.1 C389.2 C390.1 C391.1 C392.1 C393.2 C394.2 C395.2 C396.1 C397.1 C398.2 C399.2 C400.1 C401.1 C402.2 C403.2 C404.1 C405.1 C406.2 C407.2 C408.1 C409.1 C410.2 C411.2 C412.1 C413.1 C414.2 C415.2 C416.1 C417.2 C418.2 C419.2 C420.2 C421.2 C422.2 C423.2 CON2.10 CON3.10 CON5.1 CON5.7 CON5.33 CON5.39 CON5.45 CON5.51 CON5.57 CON5.63 CON5.69 CON5.75 CON6.7 CON6.10 CON6.13 CON6.16 CON6.19 CON6.22 CON6.25 CON6.30 CON6.33 CON6.37 CON6.40 CON6.41 CON6.42 CON7.12 CON7.14 CON7.16 CON7.23 CON7.30 CON7.37 CON7.42 CON7.46 CON7.47 CON8.6 CON8.10 CON8.11 CON8.12 CON8.13 CON9.1 CON9.4 CON9.7 CON9.10 CON9.13 CON9.16 CON9.19 CON9.23 CON9.24 CON10.1 CON10.4 CON10.7 CON10.10 CON10.13 CON10.16 CON10.19 CON10.23 CON10.24 CON11.1 CON11.4 CON11.7 CON11.10 CON11.13 CON11.16 CON11.19 CON11.23 CON11.24 CON12.1 CON12.4 CON12.7 CON12.10 CON12.13 CON12.16 CON12.19 CON12.23 CON12.24 CON13.7 CON13.10 CON13.13 CON13.16 CON13.19 CON13.22 CON13.25 CON13.30 CON13.33 CON13.37 CON13.40 CON13.41 CON13.42 CON14.7 CON14.10 CON14.13 CON14.16 CON14.19 CON14.22 CON14.25 CON14.30 CON14.33 CON14.37 CON14.40 CON14.41 CON14.42 CON15.32 CON15.38 CON15.41 CON15.42 CON15.48 CON15.62 CON15.63 CON15.69 CON15.75 CON15.80 CON15.81 CON15.87 CON15.97 CON15.103 CON15.109 CON15.110 CON15.111 CON15.115 CON15.116 CON15.121 CON15.122 CON16.6 CON16.12 CON16.18 CON16.19 CON16.23 CON16.28 CON16.31 CON16.36 CON16.40 CON16.44 CON16.46 CON16.47 CON16.51 CON16.57 CON16.59 CON16.61 CON16.62 CON16.64 CON16.66 CON16.67 CON16.68 CON16.72 CON16.73 CON16.78 CON16.79 CON16.85 CON16.88 CON16.91 CON16.94 CON16.97 CON16.100 CON16.103 CON16.106 CON16.109 CON16.112 CON16.115 CON16.118 CON16.121 CON16.122 CON17.5 CON17.12 CON17.16 CON17.19 CON17.23 CON17.29 CON17.30 CON17.35 CON17.41 CON17.47 CON17.48 CON17.52 CON17.53 CON17.56 CON17.57 CON17.58 CON17.60 CON17.63 CON17.67 CON17.68 CON17.70 CON17.72 CON17.73 CON17.76 CON17.87 CON17.89 CON17.90 CON17.91 CON17.93 CON17.95 CON17.97 CON17.99 CON17.101 CON17.103 CON17.104 CON17.105 CON17.107 CON17.109 CON17.111 CON17.113 CON17.118 CON17.120 CON17.121 CON17.122 CON18.5 CON18.6 CON18.11 CON18.12 CON18.17 CON18.18 CON18.23 CON18.24 CON18.29 CON18.30 CON18.35 CON18.41 CON18.44 CON18.47 CON18.52 CON18.53 CON18.56 CON18.59 CON18.60 CON18.64 CON18.68 CON18.73 CON18.78 CON18.84 CON18.87 CON18.89 CON18.90 CON18.91 CON18.96 CON18.97 CON18.99 CON18.104 CON18.105 CON18.107 CON18.108 CON18.109 CON18.110 CON18.111 CON18.112 CON18.114 CON18.116 CON18.117 CON18.119 CON18.120 CON18.121 CON18.122 D1.1 D1.2 D1.3 D1.7 D2.2 D3.2 D6.3 D6.8 D7.3 D7.8 D8.2 D9.2 D10.3 D10.8 D11.3 D11.8 D12.2 D13.2 D14.2 D15.2 D16.2 D17.2 D18.2 D19.2 D20.2 D21.2 D23.3 D24.3 D25.2 D26.2 D27.2 D28.2 D29.2 FL1.B1 FL2.3 FL3.B1 FL4.B1 FL5.B1 FL6.B1 FL7.B1 FL8.B1 FL9.B1 FL10.B1 FL11.B1 FL12.B1 FL13.B1 FL14.B1 FL15.B1 J1.1 J1.2 J1.3 J1.4 J1.5 J1.6 J1.7 J1.8 J1.A1 J1.A12 J1.B1 J1.B12 J2.2 J3.1 J4.1 J4.2 J4.3 J4.4 J4.5 J4.6 J4.7 J4.8 J4.A1 J4.A12 J4.B1 J4.B12 J5.1 J5.2 J5.3 J5.4 J5.5 J5.6 J5.7 J5.8 J5.A1 J5.A12 J5.B1 J5.B12 J9.3 J12.1 J14.2 J18.2 J22.1 J23.5 J23.6 J24.3 J25.3 J26.2 J28.3 J29.3 J33.1 J33.2 J38.1 J39.1 J43.4 J45.1 J46.1 J47.2 J48.1 J49.1 J50.2 J51.2 J53.3 LED1.2 LED2.1 LED3.1 LED5.1 MH1.1 P1.1 P1.2 P1.3 P1.4 P1.5 P1.6 P1.7 P1.8 P1.A1 P1.A12 P1.B1 P1.B12 P2.1 P2.2 P2.3 P2.4 P2.5 P2.6 P2.7 P2.8 P2.A1 P2.A12 P2.B1 P2.B12 Q5.2 Q6.2 Q7.2 Q8.2 Q14.2 Q15.2 Q16.1 Q17.2 Q18.2 Q19.2 R4.2 R9.2 R15.2 R30.1 R34.1 R35.1 R40.1 R45.1 R46.1 R48.1 R49.1 R51.1 R54.1 R61.2 R62.2 R71.1 R72.2 R74.2 R82.2 R90.2 R101.2 R102.2 R103.2 R104.2 R105.2 R106.2 R107.2 R108.2 R115.2 R123.2 R134.2 R135.2 R136.2 R137.2 R138.2 R139.2 R140.2 R141.2 R145.1 R146.1 R152.1 R155.1 R156.1 R159.1 R161.1 R167.1 R170.1 R171.1 R174.1 R175.1 R177.1 R178.1 R179.1 R180.1 R181.1 R182.1 R199.2 R206.1 R248.1 R252.2 R253.2 R262.2 R271.2 R287.2 R291.2 R292.2 R301.2 R322.1 R326.1 R334.1 R335.1 R338.1 R343.1 R366.1 R391.1 R392.1 R393.1 R396.1 R404.1 R405.1 R406.1 R407.1 R410.1 R412.1 R426.1 R429.2 R430.2 R433.2 R434.1 R440.1 R470.1 R471.1 R475.1 R476.1 R477.1 R510.1 R524.1 R525.2 R528.1 R547.1 R548.1 R549.1 R550.1 R551.1 R552.1 R553.1 R554.1 R564.1 R565.1 R566.1 R568.1 R569.1 R573.1 R574.1 R578.1 R580.1 R584.1 R586.1 R591.1 R592.1 R597.1 R598.1 R599.2 R602.1 R603.2 R604.1 R605.2 R607.2 R608.2 S2.1 S3.2 S5.2 S6.1 S7.6 S7.7 S7.8 S8.1 TP41.1 TP42.1 TP43.1 U1.4 U1.11 U1.14 U1.27 U1.33 U2.3 U3.3 U3.7 U4.7 U4.8 U4.21 U4.49 U5.3 U6.3 U7.11 U7.12 U7.14 U7.31 U7.34 U7.35 U7.39 U8.1 U8.2 U8.3 U8.4 U8.7 U9.27 U10.49 U11.49 U12.1 U12.9 U13.10 U14.5 U14.11 U14.20 U14.21 U15.1 U15.9 U16.10 U17.5 U17.11 U17.20 U17.21 U18.1 U18.9 U19.25 U21.23 U21.25 U22.8 U22.13 U23.6 U24.6 U25.1 U26.2 U27.2 U27.5 U27.15 U28.1 U29.4 U29.17 U29.20 U29.24 U29.33 U30.4 U31.4 U32.6 U33.2 U34.8 U34.13 U35.9 U35.25 U36.1 U36.3 U36.6 U36.9 U37.3 U38.2 U39.1 U40.1 U41.1 U42.1 U43.6 U44.2 U45.2 U46.2 U47.3 U48.4 U48.7 U49.A6 U49.C4 U49.E7 U49.G5 U49.H10 U49.J5 U49.K8 U49.N2 U49.N5 U49.P4 U49.P6 U50.2 U51.10 U52.4 U53.4 U53.7 U54.2 U55.2 U56.4 U57.4 U58.4 U59.4 U60.4 U61.4 U62.3 U63.2 U64.2 U65.2 U66.2 U67.2 U68.2 U69.2 U70.2 U71.2 U72.6 U72.9 U72.12 U73.6 U73.9 U73.12 U74.6 X1.2 Y1.2 Y1.4 Y2.2 Y2.4 | length 11746.7
  Top Layer w3: U49.N2@4405.57,4952.14 4415.25,4942.46 4415.25,4917.35 v1(4415.78,4916.82)
  Top Layer w4: v1(1645.11,4997.68) 1646.62,4999.19 U47.3@1678.3,4999.19 1699.1,4999.19 v1(1711.31,4986.98) ; v1(4300.03,2621.23) 4301.42,2622.62 4313.23,2622.62 4320.87,2614.98 CON18.73@4320.87,2565.4 ; v1(4516.3,3611.6) 4517.12,3612.42 CON16.68@4517.12,3668.45 ; v1(4555.67,3611.6) 4556.49,3612.42 CON16.72@4556.49,3668.45 ; CON16.78@4615.54,3668.45 4615.54,3593.17 v1(4616.14,3592.57)
  Top Layer w5: v1(2447.12,2803.73) 2450.79,2800.06 CON17.104@2450.79,2750.44 v1@2450.79,2689.88 ; v1@2588.59,2689.88 CON17.90@2588.59,2752.01 ; CON15.32@2588.59,3665.31 v1@2588.59,3727.44 ; v1@2647.64,3606.32 CON15.38@2647.64,3668.45 ; v1@2687.01,3606.32 CON15.42@2687.01,3668.45 ; CON15.41@2687.01,3850.35 v1@2687.01,3912.48 ; v1@2726.38,2689.88 CON17.76@2726.38,2752.01 ; CON15.48@2746.07,3668.45 2746.07,3585.45 v1(2747.28,3584.23) ; CON15.62@2883.86,3668.45 2883.86,3587.81 v1(2886.08,3585.59) ; v1(2901.56,3910.99) 2903.55,3909 CON15.63@2903.55,3851.92 ; CON17.57@2903.55,2563.83 2903.55,2617 v1(2913.53,2626.98) ; CON17.53@2942.92,2563.83 2942.92,2621.35 v1(2943.07,2621.51) ; CON15.69@2962.6,3850.35 v1@2962.6,3912.48 ; v1@3001.97,2504.84 CON17.47@3001.97,2566.97 ; CON15.75@3021.66,3850.35 v1@3021.66,3912.48 ; v1@3061.03,2504.84 CON17.41@3061.03,2566.97 ; CON15.80@3061.03,3665.31 v1@3061.03,3727.44 ; CON15.81@3080.62,3852.72 v1@3080.62,3914.85 ; v1@3120.08,2504.84 CON17.35@3120.08,2566.97 ; v1(3135.93,3912.04) 3139.77,3908.2 CON15.87@3139.77,3850.35 ; v1@3179.14,2504.84 CON17.29@3179.14,2566.97 ; v1(3237.76,2495.44) 3238.19,2495.87 CON17.23@3238.19,2566.97 ; CON15.97@3238.19,3850.35 v1@3238.19,3912.48 ; CON17.19@3277.56,2566.97 3277.56,2491.37 v1(3277.7,2491.23) ; CON15.103@3297.25,3850.35 3297.25,3918.62 v1(3308.59,3929.97) ; CON15.110@3356.3,3665.31 v1@3356.3,3727.44 ; CON15.109@3356.3,3850.35 3356.3,3905.15 v1(3359.68,3908.53) ; v1(3414.89,3908.17) v1@3415.36,3907.7 ; v1@3415.36,2504.84 CON17.5@3415.36,2566.97 ; CON15.116@3415.36,3665.31 v1@3415.36,3727.44
  Top Layer w6: v1@2805.12,2509.5 CON17.67@2805.12,2565.4 ; CON17.63@2844.49,2565.4 2844.49,2612.29 v1(2857.38,2625.18) ; CON17.16@3316.93,2750.44 v1@3316.93,2810.35 ; CON17.12@3356.3,2748.07 v1@3356.3,2807.98 ; v1(3359.68,3908.53) 3370.1,3908.53 3375.99,3902.65 CON15.111@3375.99,3851.92 ; CON15.115@3415.36,3851.92 v1@3415.36,3907.7 ; CON18.120@3868.11,2750.44 v1@3868.11,2810.35 ; CON18.108@3986.22,2750.44 v1@3986.22,2810.35 ; CON18.104@4025.59,2750.44 v1@4025.59,2810.35 ; CON18.96@4104.33,2750.44 v1@4104.33,2810.35 ; v1(4151.25,5049.47) 4151.25,5048.98 U49.A6@4169.35,5030.88 ; CON18.90@4163.39,2750.44 v1@4163.39,2827.49 ; CON18.84@4222.44,2750.44 v1@4222.44,2810.35 ; CON18.78@4281.5,2750.44 v1@4281.5,2827.49 ; CON18.68@4379.71,2756.31 v1@4379.71,2816.22 ; v1@4458.66,2504.73 CON18.59@4458.66,2565.4 ; CON18.56@4498.03,2750.44 v1(4498.03,2847.18) ; CON18.53@4517.72,2565.4 4517.72,2623.49 v1(4537.73,2643.51) ; CON16.67@4517.72,3851.92 v1@4517.72,3907.7 ; CON18.52@4537.4,2750.44 4537.4,2845.37 v1(4537.75,2845.72) ; v1@4576.77,2504.73 CON18.47@4576.77,2565.4 ; CON16.73@4576.77,3851.92 v1@4576.77,3907.7 ; v1(4589.74,2679.3) 4616.14,2705.7 CON18.44@4616.14,2750.44 ; v1@4635.83,2504.73 CON18.41@4635.83,2565.4 ; CON16.79@4635.83,3851.92 4635.83,3796.12 v1(4653.85,3778.1) ; v1@4694.88,2504.73 CON18.35@4694.88,2565.4 ; CON16.85@4694.88,3851.92 v1@4694.88,3907.7 ; v1@4753.94,2504.73 CON18.29@4753.94,2565.4 ; CON18.30@4753.94,2750.44 v1(4753.95,2828.9) ; CON16.91@4753.94,3851.92 v1@4753.94,3907.7 ; CON16.94@4773.62,3666.88 v1@4773.62,3722.66 ; v1@4812.99,2504.73 CON18.23@4812.99,2565.4 ; CON18.24@4812.99,2750.44 v1(4813.01,2828.9) ; CON16.97@4812.99,3851.92 v1@4812.99,3907.7 ; CON16.100@4832.68,3666.88 4832.68,3719.26 v1(4835.28,3721.86) ; v1(4871.43,2505.49) 4872.05,2506.11 CON18.17@4872.05,2565.4 ; CON18.18@4872.05,2750.44 v1(4872.06,2828.9) ; CON16.103@4872.05,3851.92 v1@4872.05,3907.7 ; v1(4930.95,2504.58) 4931.1,2504.73 CON18.11@4931.1,2565.4 ; CON18.12@4931.1,2750.44 v1(4931.12,2828.9) ; CON16.109@4931.1,3851.92 v1@4931.1,3907.7 ; CON18.6@4990.16,2750.44 v1(4990.17,2828.9) ; CON16.115@4990.16,3851.92 v1@4990.16,3907.7
  Top Layer w8: CON9.19@1728.05,6095.14 1728.05,6057 v1(1728.31,6056.75) ; CON9.16@1787.11,6095.14 1787.11,6057 v1(1787.36,6056.75) ; CON9.13@1846.16,6095.14 1846.16,6059.14 v1(1846.61,6058.69) ; CON9.10@1905.22,6095.14 1905.22,6137.31 v1(1907.63,6139.72) ; v1(2023.35,6034.3) CON9.4@2023.33,6095.14 ; v1(2082.12,6133.54) 2082.38,6133.29 CON9.1@2082.38,6095.14 ; U1.33@2525.41,479.9 v1(2535.26,489.75) ; U49.C4@4208.72,4991.51 4227.8,5010.59 v1(4228.83,5010.59) ; U49.G5@4287.46,5011.2 4287.46,5023.54 4299.85,5035.94 v1(4306.11,5035.94) 4326.83,5015.21 U49.J5@4326.83,5011.2 ; U49.K8@4346.51,5070.25 4364.94,5070.25 v1(4366.1,5069.08) ; U49.P4@4425.25,4991.51 U49.N5@4405.57,5011.2 U49.P6@4425.25,5030.88 4440.42,5030.88 v1(4443.26,5033.72) ; v1(6006.74,4753.82) 6009.56,4756.65 U32.6@6009.56,4783.08 ; v1(6014.35,5017.04) 6018.8,5021.49 U43.6@6018.8,5043.55 ; v1(6146.34,240.42) 6146.6,240.16 CON12.1@6146.6,202.02 ; v1(6323.51,240.42) 6323.77,240.16 CON12.10@6323.77,202.02 ; v1(6382.56,240.42) 6382.82,240.16 CON12.13@6382.82,202.02 ; v1(6441.62,240.42) 6441.88,240.16 CON12.16@6441.88,202.02 ; v1(6500.67,240.42) 6500.93,240.16 CON12.19@6500.93,202.02 ; v1(6849.43,438.34) 6849.69,438.6 CON10.1@6887.83,438.6 ; v1(6849.43,497.39) 6849.69,497.65 CON10.4@6887.83,497.65 ; v1(6849.43,556.45) 6849.69,556.71 CON10.7@6887.83,556.71 ; v1(6849.43,615.5) 6849.69,615.76 CON10.10@6887.83,615.76 ; v1(6849.43,674.56) 6849.69,674.82 CON10.13@6887.83,674.82 ; v1(6849.43,792.67) 6849.69,792.93 CON10.19@6887.83,792.93 ; v1(6849.43,1225.31) 6849.69,1225.57 CON11.1@6887.83,1225.57 ; v1(6849.43,1284.37) 6849.69,1284.62 CON11.4@6887.83,1284.62 ; v1(6849.43,1343.42) 6849.69,1343.68 CON11.7@6887.83,1343.68 ; v1(6849.43,1402.48) 6849.69,1402.74 CON11.10@6887.83,1402.74 ; v1(6849.43,1461.53) 6849.69,1461.79 CON11.13@6887.83,1461.79 ; v1(6849.43,1520.59) 6849.69,1520.85 CON11.16@6887.83,1520.85 ; v1(6849.43,1579.64) 6849.69,1579.9 CON11.19@6887.83,1579.9 ; v1(6853.77,733.33) 6854.31,733.87 CON10.16@6887.83,733.87
  Top Layer w10: J1.B1@338.92,1103.14 J1.B1@340.89,1105.11 ; J1.B12@338.92,1323.62 J1.B12@340.88,1321.65 ; v1(486.28,1238.96) 486.89,1238.35 FL1.B1@486.89,1213.83 v1@486.89,1189.32 ; U7.31@607.06,1141.62 629.11,1141.62 U7.39@682.85,1087.88 736.59,1141.62 U7.14@758.64,1141.62 ; C138.1@893.57,3743.82 v1@893.57,3770.45 ; v1@894.68,3394.77 D6.3@921.3,3394.77 ; v1@894.68,3589.92 D7.3@921.3,3589.92 ; v1(897.35,4952.93) 897.51,4952.76 C164.1@897.51,4926.14 ; v1@898.62,4577.08 D10.3@925.24,4577.08 ; v1@898.62,4772.24 D11.3@925.24,4772.24 ; D6.8@957.3,3394.77 v1@983.92,3394.77 ; D7.8@957.3,3589.92 v1@983.92,3589.92 ; D10.8@961.24,4577.08 v1@987.86,4577.08 ; D11.8@961.24,4772.24 v1@987.86,4772.24 ; v1(1143.04,3663.84) 1143.82,3664.62 C129.2@1164.78,3664.62 ; v1(1151.42,4897.33) 1152.71,4896.05 C152.1@1172.36,4896.05 ; v1@1151.72,4870.97 C154.2@1172.18,4870.97 ; v1(1158.89,3349.31) 1159.49,3349.91 R90.2@1178.04,3349.91 ; v1(1169.55,4516.18) 1181.98,4528.61 R123.2@1181.98,4532.22 ; C156.2@1171.34,4846.01 1171.34,4834.16 v1(1180.97,4824.53) ; v1(1226.64,3690.96) 1235.78,3681.83 R108.2@1250.74,3681.83 ; v1(1233.55,4874.15) 1243.55,4864.14 R141.2@1254.68,4864.14 ; v1(1280.74,3697.75) 1280.84,3697.65 R107.2@1280.84,3681.83 ; v1(1284.55,4881.12) 1284.79,4880.88 R140.2@1284.79,4864.14 ; R106.2@1310.75,3681.83 1310.75,3698.35 v1(1310.83,3698.42) ; R139.2@1314.7,4864.14 1314.7,4880.1 v1(1315.54,4880.94) ; v1(1371.28,3697.73) 1371.42,3697.58 C139.2@1371.42,3681.84 ; C165.2@1375.36,4864.15 1375.36,4880.01 v1(1375.44,4880.08) ; C134.1@1402.13,3681.84 1402.13,3701.72 v1(1402.82,3702.41) ; C125.2@1427.77,3681.84 1427.77,3696.79 v1(1428.65,3697.67) 1428.65,3712.9 R103.2@1428.59,3712.96 ; C124.2@1459.11,3681.84 1459.11,3697.41 v1(1458.94,3697.58) 1458.94,3711.26 1458.78,3711.42 1459.62,3712.27 R102.2@1459.11,3712.79 ; C150.2@1463.05,4864.15 1462.88,4864.32 v1(1462.88,4878.98) 1463.05,4879.15 R135.2@1463.05,4894.86 ; v1(1492.33,4182.38) 1502.07,4172.64 U36.3@1502.07,4160.81 1502.07,4133.25 U36.9@1511.91,4123.41 ; R74.2@1876.33,463.38 1899.24,463.38 v1(1900.31,464.45) ; U1.27@2440.76,519.3 2505.71,519.3 v1(2535.26,489.75) ; R4.2@2495.67,665.73 2495.67,677.96 v1(2500.2,682.49) ; U1.4@2525.41,395.25 U1.33@2525.41,479.9 ; v1(2542.98,289.04) 2544.17,290.23 R9.2@2544.17,308.23 ; v1(2567.38,682) 2567.58,681.79 R15.2@2567.58,666.02 ; U1.11@2629.76,460.2 2564.81,460.2 v1(2535.26,489.75) ; U1.14@2629.76,519.3 2564.81,519.3 v1(2535.26,489.75) ; v1@2726.21,5817.52 FL6.B1@2752.36,5817.52 v1@2778.52,5817.52 ; J4.8@2787.85,5875.98 2812.46,5875.98 J4.A12@2812.46,5914.96 2812.46,5960.63 J4.B1@2810.49,5962.6 ; v1@2815.91,5816.57 FL8.B1@2842.06,5816.57 v1@2868.21,5816.57 ; v1@2894.65,5816.57 FL4.B1@2920.8,5816.57 v1@2946.95,5816.57 ; FL5.B1@3013.14,5817.43 v1@3039.29,5817.43 ; J4.A1@3029,5914.96 3029,5960.64 J4.B12@3030.96,5962.6 ; v1@3062.93,5817.52 FL7.B1@3089.08,5817.52 v1@3115.23,5817.52 ; FL3.B1@3496.61,478.52 3521.15,478.52 v1(3527.28,484.65) ; v1@3708.06,5820.69 FL15.B1@3732.58,5820.69 v1@3759.08,5820.69 ; CON6.7@4022.06,209.68 4022.06,177.74 v1(4022.61,177.19) ; CON6.10@4081.11,209.68 4081.11,176.59 v1(4081.43,176.27) ; CON6.13@4140.17,209.68 4140.17,174.7 v1(4141.15,173.72) ; FL11.B1@4170.84,5821.63 v1@4196.99,5821.63 ; v1(4196.1,170.96) 4199.22,174.09 CON6.16@4199.22,209.68 ; J5.8@4206.32,5880.1 4230.93,5880.1 4230.93,5964.74 J5.B1@4228.96,5966.71 ; v1@4234.38,5820.69 FL13.B1@4260.53,5820.69 4290.01,5820.69 v1(4290.75,5821.43) ; v1(4254.65,180.76) 4258.28,184.38 CON6.19@4258.28,209.68 ; U49.H10@4307.14,5109.62 4307.14,5115.63 v1(4320.97,5129.46) ; CON6.22@4317.33,209.68 4317.33,181.56 4335.78,163.11 v1(4337.78,163.11) ; FL9.B1@4339.27,5820.69 4358.45,5820.69 4368.39,5810.76 4381.17,5810.76 v1(4381.87,5810.05) ; FL10.B1@4431.61,5821.55 v1@4457.77,5821.55 ; J5.A1@4447.47,5919.08 4447.47,5964.75 J5.B12@4449.43,5966.71 ; v1@4481.4,5821.63 FL12.B1@4507.56,5821.63 4533.71,5821.63 v1(4534.15,5821.19) ; CON13.33@5045.55,6091.51 5045.55,6060.88 v1(5054.34,6052.09) ; CON13.30@5104.61,6090.59 5104.61,6055.97 v1(5109.54,6051.04) ; v1(5150.25,1397.78) 5150.25,1397.69 5150.82,1397.12 C261.1@5173.47,1397.12 ; CON13.25@5203.03,6090.59 5203.03,6147.2 v1(5203.36,6147.53) ; CON13.22@5262.09,6090.59 5262.09,6067.35 5270.21,6059.22 v1(5270.21,6054.9) ; v1(5321.06,6054.32) 5321.14,6054.4 CON13.19@5321.14,6090.59 ; CON13.16@5380.2,6090.59 5380.2,6054.28 v1(5380.3,6054.18) ; CON13.13@5439.25,6090.59 5439.25,6054.94 v1(5440.01,6054.18) ; v1(5497.92,6054.43) 5498.31,6054.83 CON13.10@5498.31,6090.59 ; CON14.40@5921.17,6090.59 5921.17,6145.67 v1(5921.32,6145.82) ; CON14.37@5980.22,6090.59 5980.22,6051.57 v1(5981.75,6050.05) ; R392.1@6041.54,4903.55 6060.96,4903.55 v1(6063.47,4901.04) ; v1(6053.49,6145.43) 6058.96,6139.96 CON14.33@6058.96,6090.59 ; CON14.30@6118.02,6090.59 6118.02,6066.48 6130.72,6053.78 v1(6138.83,6053.78) ; CON12.4@6205.66,202.02 6205.66,240.57 v1(6205.93,240.85) ; CON12.7@6264.71,202.02 6264.71,241.14 v1(6265.02,241.44)
  Top Layer w12: P1.A12@3604.95,384.25 3604.95,338.58 P1.B1@3606.92,336.61 ; P2.B1@3622.27,5962.6 3624.24,5960.63 P2.A12@3624.24,5914.96
  Top Layer w15: J1.B1@340.89,1105.11 J1.A12@386.55,1105.11 ; J1.B12@340.88,1321.65 J1.A1@386.55,1321.65
  Bottom Layer w4: v1(289.01,2649.1) 293.82,2653.91 C414.2@309.48,2653.91 ; v1(307.35,2609.45) 307.35,2626.4 C416.1@309.49,2628.54 ; U37.3@6362.83,5365.12 6362.83,5337.84 v1(6364.93,5335.74)
  Bottom Layer w6: v1(3367.89,5540.05) 3376.55,5531.4 J38.1@3480.76,5531.4 ; v1(3800.97,103.69) 3808.72,103.69 3823.84,88.57 U5.3@3823.84,67.94 ; v1(5163.98,5483.6) 5166.1,5485.72 R404.1@5183.08,5485.72 ; v1(5164.31,5552.39) 5179.12,5552.39 R405.1@5183.1,5548.41
  Bottom Layer w8: v1(1493,871.66) 1493,856.84 1496.91,852.93 U72.6@1505.8,852.93 ; v1(2090.62,240.81) 2093.52,243.71 R604.1@2113.98,243.71 ; v1(2090.83,208.21) 2093.06,210.43 R252.2@2114.11,210.43 ; v1(2118.48,135.39) 2119.38,136.29 R599.2@2138.44,136.29 ; v1(2174.14,282.38) 2174.14,259.79 2188.96,244.97 U73.6@2194.85,244.97 ; v1(2585.98,6099.97) 2588.54,6099.97 2601.08,6087.44 U13.10@2601.08,6073.52 ; v1(4012.52,6093.06) 4015.87,6093.06 4025.8,6083.13 U16.10@4025.8,6067.99 ; v1(4306.11,5035.94) 4319.29,5049.12 C353.2@4319.29,5061.65 4326.72,5069.08 v1(4366.1,5069.08) ; v1(4509.78,68.27) 4511.7,70.2 C228.2@4511.7,91.18 ; R262.2@4517.42,2645.01 4536.23,2645.01 v1(4537.73,2643.51) ; C225.1@4537.13,91.18 4537.13,69.61 v1(4539.09,67.65) ; v1(5447.21,3537.05) 5447.72,3536.54 FL14.B1@5447.72,3504.2 5447.72,3474.38 v1(5447.96,3474.14) ; v1(5706.29,3143.56) 5712.61,3137.24 C367.2@5712.61,3124.06 5712.61,3088.52 U50.2@5712.05,3087.95 ; C401.1@6512.3,387.84 6538.08,387.84 6539.8,389.56 6541.42,387.94 v1(6567.2,387.94) ; v1(6695.56,550.21) 6703.65,542.11 C398.2@6703.65,527.32
  Bottom Layer w10: C74.1@1720.55,5914.65 1738.77,5896.43 v1(1741.05,5896.43) ; v1(1739.76,6028.17) 1739.76,6022.1 1753.62,6008.24 U31.4@1773.32,6008.24 ; v1(1933.76,5654.72) 1957,5654.72 R471.1@1961.1,5650.62 ; R470.1@1961.1,5587.99 1961.1,5571.01 v1(1961.18,5570.93) ; v1(1969.85,5760.26) 1969.85,5772.85 1982.42,5785.43 U34.8@2019.09,5785.43 ; v1(2611.43,5948.06) 2611.43,5966.42 R152.1@2614.04,5969.02 ; U51.10@3768.41,228.43 3768.41,206.19 3774.03,200.57 v1(3774.03,194.09) ; v1(3928.28,6049.86) 3929.27,6050.85 R171.1@3947.35,6050.85 ; v1(4024.83,5954.11) 4024.83,5971.39 R167.1@4026.99,5973.55 ; C310.1@4172.32,5020.93 4172.32,5028.41 v1(4151.25,5049.47) 4152.34,5050.56 C357.2@4184.62,5050.56 ; v1(4254.65,180.76) 4261.99,188.09 U58.4@4293.42,188.09 ; C355.2@4305.52,5112.23 4320.97,5127.68 v1(4320.97,5129.46) ; v1(4443.26,5033.72) 4444.23,5032.75 C359.2@4464.24,5032.75 ; v1(4459.57,4944.41) 4476.36,4944.41 4485.4,4953.45 C358.2@4485.4,4971.39 ; v1(5149.28,5763.5) 5164.62,5763.5 C408.1@5170.27,5769.15 ; v1(5150.53,5790.73) 5154.17,5794.36 C406.2@5170.45,5794.36 ; v1(5166.51,6028.93) 5168.49,6030.91 5168.49,6063.68 C405.1@5170.3,6065.49 ; C407.2@5189.1,6109.37 5203.36,6123.63 v1(5203.36,6147.53) ; v1(5233.01,5697.97) 5233.01,5683.93 5237.9,5679.04 U22.8@5251.05,5679.04 ; U59.4@5266.5,6012.35 5266.5,6051.18 v1(5270.21,6054.9) ; v1(5357.6,3093.87) 5357.89,3093.58 R335.1@5376.25,3093.58 ; U35.25@5539.9,3041.71 U35.9@5591.4,3041.71 ; C412.1@5828.47,5948.32 5828.47,5966.52 v1(5829.89,5967.94) ; C410.2@5854.61,5948.64 5854.61,5966.21 v1(5855.79,5967.38) ; v1(6024.74,5860.95) 6033.93,5851.76 U60.4@6078.35,5851.76 ; v1(6107.64,5953.14) 6111.16,5949.61 C409.1@6131.88,5949.61 ; C233.2@6169.17,4023.65 6169.17,4032.2 6187.67,4050.71 v1(6197.12,4050.71) ; v1(6177.53,5913.21) 6178.18,5913.86 C411.2@6178.18,5932.14 ; C404.1@6214.09,386.12 6214.17,386.2 6214.17,405.13 v1(6214.28,405.24) ; C402.2@6239.98,385.83 6239.98,394.87 6249.61,404.49 v1(6262.68,404.49) ; U57.4@6459.98,288.59 6459.98,265.57 v1(6461.04,264.51) ; v1(6702.01,482.69) 6703.15,483.83 C400.1@6703.15,501.64 ; U56.4@6800.25,754.21 6800.25,766.25 6803.08,769.08 v1(6827,769.08)
  Bottom Layer w12: U21.23@5408.49,2442.7 5436.05,2442.7 v1(5445.89,2452.54)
